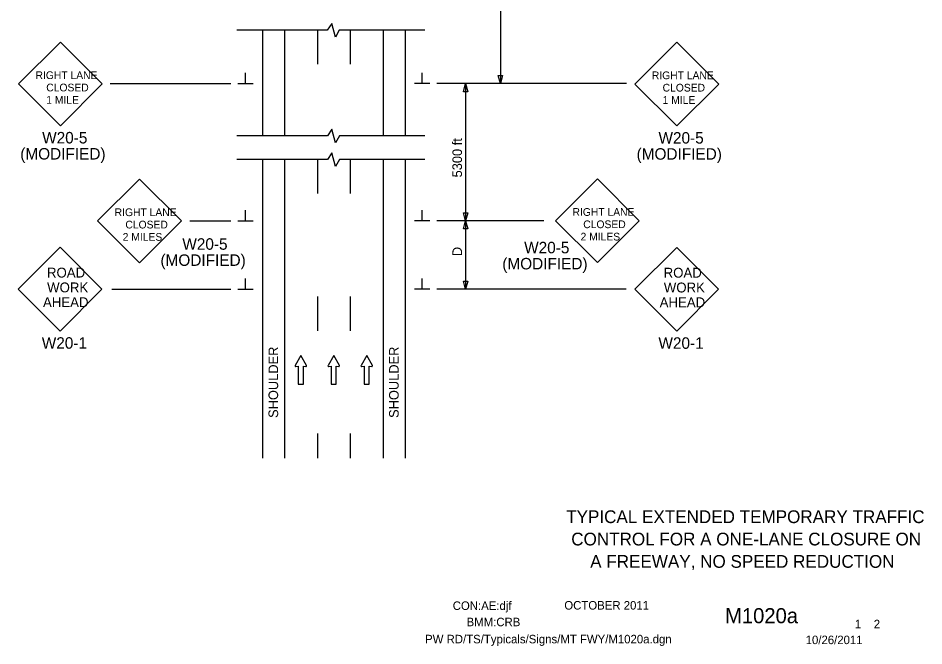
# Model space of a CAD drawing. Extents: x 16774 to 18475, y 7218 to 8206.
# Drawn here: x 16774 to 17434, y 7218 to 7676 of the extents above; entities that cross this region are included whole.
import ezdxf

# ---------------------------------------------------------------- set-up
doc = ezdxf.new("R2010")
doc.units = 0
for name, color, linetype in [('ALI_LEGAL_EX', 7, 'Continuous'), ('BORDER', 7, 'Continuous'), ('BORDER_SIGNAL_WO', 7, 'Continuous'), ('MT_SCRATCH_LEVEL_E', 7, 'Continuous'), ('PAVT_EDGE_EX', 7, 'Continuous'), ('TRAFFIC_SIGNS_PR', 7, 'Continuous'), ('TYPICAL_TEXT_DIMEN_PR', 7, 'Continuous')]:
    doc.layers.add(name, color=color, linetype=linetype)

msp = doc.modelspace()

# ---------------------------------------------------------------- linework, layer by layer
at = {"layer": 'ALI_LEGAL_EX'}
for points in [[(16992.01, 7667.25), (16992.01, 7642.25)], [(17016.01, 7667.25), (17016.01, 7642.25)], [(16992.01, 7572.96), (16992.01, 7547.96)], [(17016.01, 7572.96), (17016.01, 7547.96)], [(16992.01, 7472.96), (16992.01, 7447.96)], [(17016.01, 7472.96), (17016.01, 7447.96)], [(16992.01, 7372.96), (16992.01, 7355.1)], [(17016.01, 7372.96), (17016.01, 7355.1)]]:
    msp.add_lwpolyline(points, dxfattribs=at)
at = {"layer": 'MT_SCRATCH_LEVEL_E'}
for p, q in [((16980.01, 7429.81), (16975.89, 7422.57)), ((16984.15, 7422.57), (16980.01, 7429.81)), ((17003.91, 7429.81), (16999.8, 7422.57)), ((17008.06, 7422.57), (17003.91, 7429.81)), ((17027.96, 7429.81), (17023.85, 7422.57)), ((17032.11, 7422.57), (17027.96, 7429.81)), ((16976.38, 7421.89), (16978.15, 7422.2)), ((16978.15, 7422.2), (16978.15, 7408.94)), ((16981.9, 7408.94), (16981.9, 7422.2)), ((16981.9, 7422.2), (16983.67, 7421.89)), ((17000.28, 7421.89), (17002.06, 7422.2)), ((17002.06, 7422.2), (17002.06, 7408.94)), ((17005.8, 7408.94), (17005.8, 7422.2)), ((17005.8, 7422.2), (17007.58, 7421.89)), ((17024.33, 7421.89), (17026.11, 7422.2)), ((17026.11, 7422.2), (17026.11, 7408.94)), ((17029.85, 7408.94), (17029.85, 7422.2)), ((17029.85, 7422.2), (17031.63, 7421.89)), ((16978.15, 7408.94), (16981.9, 7408.94)), ((17002.06, 7408.94), (17005.8, 7408.94)), ((17026.11, 7408.94), (17029.85, 7408.94))]:
    msp.add_line(p, q, dxfattribs=at)
for centre, start, end in [((16976.3, 7422.34), 150.42484, 279.96381), ((16983.74, 7422.34), 260.03619, 29.77312), ((17000.21, 7422.34), 150.42484, 279.96381), ((17007.65, 7422.34), 260.03619, 29.77312), ((17024.26, 7422.34), 150.42484, 279.96381), ((17031.7, 7422.34), 260.03619, 29.77312)]:
    msp.add_arc(centre, 0.463, start, end, dxfattribs=at)
at = {"layer": 'PAVT_EDGE_EX'}
for p, q in [((16952.01, 7667.25), (16952.01, 7590.09)), ((16968.01, 7667.25), (16968.01, 7590.09)), ((17040.01, 7667.25), (17040.01, 7590.09)), ((17056.01, 7667.25), (17056.01, 7590.09)), ((16952.01, 7572.96), (16952.01, 7355.1)), ((16968.01, 7572.96), (16968.01, 7355.1)), ((17040.01, 7572.96), (17040.01, 7355.1)), ((17056.01, 7572.96), (17056.01, 7355.1))]:
    msp.add_line(p, q, dxfattribs=at)
at = {"layer": 'TRAFFIC_SIGNS_PR'}
for p, q in [((16804.73, 7658.51), (16774.18, 7627.96)), ((16835.28, 7627.96), (16804.73, 7658.51)), ((17253.97, 7658.4), (17223.42, 7627.85)), ((17284.52, 7627.85), (17253.97, 7658.4)), ((16774.18, 7627.96), (16804.73, 7597.41)), ((16804.73, 7597.41), (16835.28, 7627.96)), ((17223.42, 7627.85), (17253.97, 7597.3)), ((17253.97, 7597.3), (17284.52, 7627.85)), ((16862.41, 7558.55), (16831.86, 7528)), ((16892.96, 7528), (16862.41, 7558.55)), ((17196.13, 7558.75), (17165.59, 7528.2)), ((17226.68, 7528.2), (17196.13, 7558.75)), ((16831.86, 7528), (16862.41, 7497.45)), ((16862.41, 7497.45), (16892.96, 7528)), ((17165.59, 7528.2), (17196.13, 7497.66)), ((17196.13, 7497.66), (17226.68, 7528.2)), ((16804.45, 7508.8), (16773.91, 7478.25)), ((16835, 7478.25), (16804.45, 7508.8)), ((17253.93, 7508.73), (17223.38, 7478.19)), ((17284.48, 7478.19), (17253.93, 7508.73)), ((16773.91, 7478.25), (16804.45, 7447.7)), ((16804.45, 7447.7), (16835, 7478.25)), ((17223.38, 7478.19), (17253.93, 7447.64)), ((17253.93, 7447.64), (17284.48, 7478.19))]:
    msp.add_line(p, q, dxfattribs=at)
at = {"layer": 'TYPICAL_TEXT_DIMEN_PR'}
for p, q in [((17125.44, 7928.14), (17125.44, 7628.14)), ((17002.52, 7672.04), (16999.26, 7667.24)), ((17005.26, 7662.1), (17002.52, 7672.04)), ((16999.26, 7667.24), (16933.32, 7667.24)), ((17008, 7667.24), (17005.26, 7662.1)), ((17070.34, 7667.24), (17008, 7667.24)), ((16939.63, 7628.14), (16939.63, 7635.93)), ((17068.38, 7628.14), (17068.38, 7635.93)), ((17125.44, 7628.14), (17123.87, 7634)), ((17123.87, 7634), (17125.44, 7634)), ((17125.44, 7634), (17127.01, 7634)), ((17127.01, 7634), (17125.44, 7628.14)), ((16840.95, 7628.14), (16929.01, 7628.14)), ((16934.01, 7628.14), (16945.26, 7628.14)), ((17074.01, 7628.14), (17062.76, 7628.14)), ((17217.4, 7628.14), (17079.01, 7628.14)), ((17098.44, 7622.28), (17100.01, 7628.14)), ((17100.01, 7628.14), (17100.01, 7528.14)), ((17100.01, 7628.14), (17101.58, 7622.28)), ((17100.01, 7622.28), (17098.44, 7622.28)), ((17101.58, 7622.28), (17100.01, 7622.28)), ((17002.61, 7594.88), (16999.35, 7590.08)), ((17005.35, 7584.94), (17002.61, 7594.88)), ((16999.35, 7590.08), (16933.41, 7590.08)), ((17008.09, 7590.08), (17005.35, 7584.94)), ((17070.43, 7590.08), (17008.09, 7590.08)), ((16999.35, 7572.94), (16933.41, 7572.94)), ((17002.61, 7577.74), (16999.35, 7572.94)), ((17005.35, 7567.8), (17002.61, 7577.74)), ((17008.09, 7572.94), (17005.35, 7567.8)), ((17070.43, 7572.94), (17008.09, 7572.94)), ((16939.63, 7528.14), (16939.63, 7535.93)), ((17068.38, 7528.14), (17068.38, 7535.93)), ((17100.01, 7528.14), (17098.44, 7534)), ((17098.44, 7534), (17100.01, 7534)), ((17100.01, 7534), (17101.58, 7534)), ((17101.58, 7534), (17100.01, 7528.14)), ((16898.96, 7528.14), (16929.01, 7528.14)), ((16934.01, 7528.14), (16945.26, 7528.14)), ((17074.01, 7528.14), (17062.76, 7528.14)), ((17157.02, 7528.14), (17079.01, 7528.14)), ((17098.44, 7522.28), (17100.01, 7528.14)), ((17100.01, 7528.14), (17100.01, 7478.14)), ((17100.01, 7528.14), (17101.58, 7522.28)), ((17100.01, 7522.28), (17098.44, 7522.28)), ((17101.58, 7522.28), (17100.01, 7522.28)), ((16939.63, 7478.14), (16939.63, 7485.93)), ((17068.38, 7478.14), (17068.38, 7485.93)), ((17100.01, 7478.14), (17098.44, 7484)), ((17098.44, 7484), (17100.01, 7484)), ((17100.01, 7484), (17101.58, 7484)), ((17101.58, 7484), (17100.01, 7478.14)), ((16842.13, 7478.14), (16929.01, 7478.14)), ((16934.01, 7478.14), (16945.26, 7478.14)), ((17074.01, 7478.14), (17062.76, 7478.14)), ((17217, 7478.14), (17079.01, 7478.14))]:
    msp.add_line(p, q, dxfattribs=at)

# ---------------------------------------------------------------- texts
at = {"layer": 'BORDER'}
for s, p in [('TYPICAL EXTENDED TEMPORARY TRAFFIC', (17173.38, 7307.65)), ('CONTROL FOR A ONE-LANE CLOSURE ON', (17177.07, 7291.35)), ('A FREEWAY, NO SPEED REDUCTION', (17190.88, 7275.05))]:
    msp.add_text(s, height=9.3, dxfattribs=at).set_placement(p)
at = {"layer": 'BORDER_SIGNAL_WO'}
for s, height, p in [('CON:AE:djf  ', 6.2, (17090.69, 7244.31)), ('    OCTOBER 2011    ', 6.2, (17162.8, 7244.59)), ('    M1020a   ', 11, (17272.86, 7234.63)), ('BMM:CRB   ', 6.2, (17100.81, 7232.42)), (' 1    2 ', 6.2, (17381.45, 7230.95)), ('PW RD/TS/Typicals/Signs/MT FWY/M1020a.dgn      ', 6.2, (17070.55, 7219.96)), ('10/26/2011    ', 6.2, (17347.93, 7219.38))]:
    msp.add_text(s, height=height, dxfattribs=at).set_placement(p)
at = {"layer": 'TRAFFIC_SIGNS_PR'}
for s, height, p in [('RIGHT LANE', 5.625, (16786.6, 7631.5)), ('RIGHT LANE', 5.625, (17235.83, 7631.39)), ('CLOSED', 5.625, (16794.42, 7622.5)), ('CLOSED', 5.625, (17243.66, 7622.39)), ('1 MILE', 5.625, (16794.41, 7613.5)), ('1 MILE', 5.625, (17243.65, 7613.39)), ('W20-5', 8.37, (16791.43, 7584.54)), ('W20-5', 8.37, (17240.66, 7584.43)), ('(MODIFIED)', 8.37, (16775.47, 7572.8)), ('(MODIFIED)', 8.37, (17224.71, 7572.69)), ('RIGHT LANE', 5.625, (16844.27, 7531.54)), ('RIGHT LANE', 5.625, (17178, 7531.75)), ('CLOSED', 5.625, (16852.1, 7522.54)), ('CLOSED', 5.625, (17185.82, 7522.75)), ('2 MILES', 5.625, (16850.13, 7513.54)), ('W20-5', 8.37, (16893.6, 7507)), ('2 MILES', 5.625, (17183.85, 7513.75)), ('W20-5', 8.37, (17142.75, 7504.42)), ('(MODIFIED)', 8.37, (16877.65, 7495.25)), ('(MODIFIED)', 8.37, (17126.8, 7492.67)), ('ROAD', 7.2, (16794.94, 7486.73)), ('ROAD', 7.2, (17244.41, 7486.66)), ('WORK', 7.2, (16795.06, 7475.93)), ('WORK', 7.2, (17244.54, 7475.86)), ('AHEAD', 7.2, (16792.04, 7465.13)), ('AHEAD', 7.2, (17241.51, 7465.06)), ('W20-1', 8.37, (16791.15, 7434.83)), ('W20-1', 8.37, (17240.62, 7434.77))]:
    msp.add_text(s, height=height, dxfattribs=at).set_placement(p)
at = {"layer": 'TYPICAL_TEXT_DIMEN_PR'}
for s, p in [('5300 ft', (17097.45, 7559.75)), ('D', (17097.45, 7502.36)), ('SHOULDER', (16963.43, 7384.35)), ('SHOULDER', (17051.29, 7384.35))]:
    msp.add_text(s, height=7, rotation=90, dxfattribs=at).set_placement(p)

doc.saveas('drawing.dxf')
